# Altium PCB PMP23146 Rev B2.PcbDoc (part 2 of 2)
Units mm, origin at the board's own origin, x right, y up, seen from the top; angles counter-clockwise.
Board outline 35 x 30 mm, 4 copper layers (Top Layer, Int1 (GND), Int2 (PWR), Bottom Layer), stack 0.912 mm thick; 83 components, 52 nets, 312 pads, 74 vias.
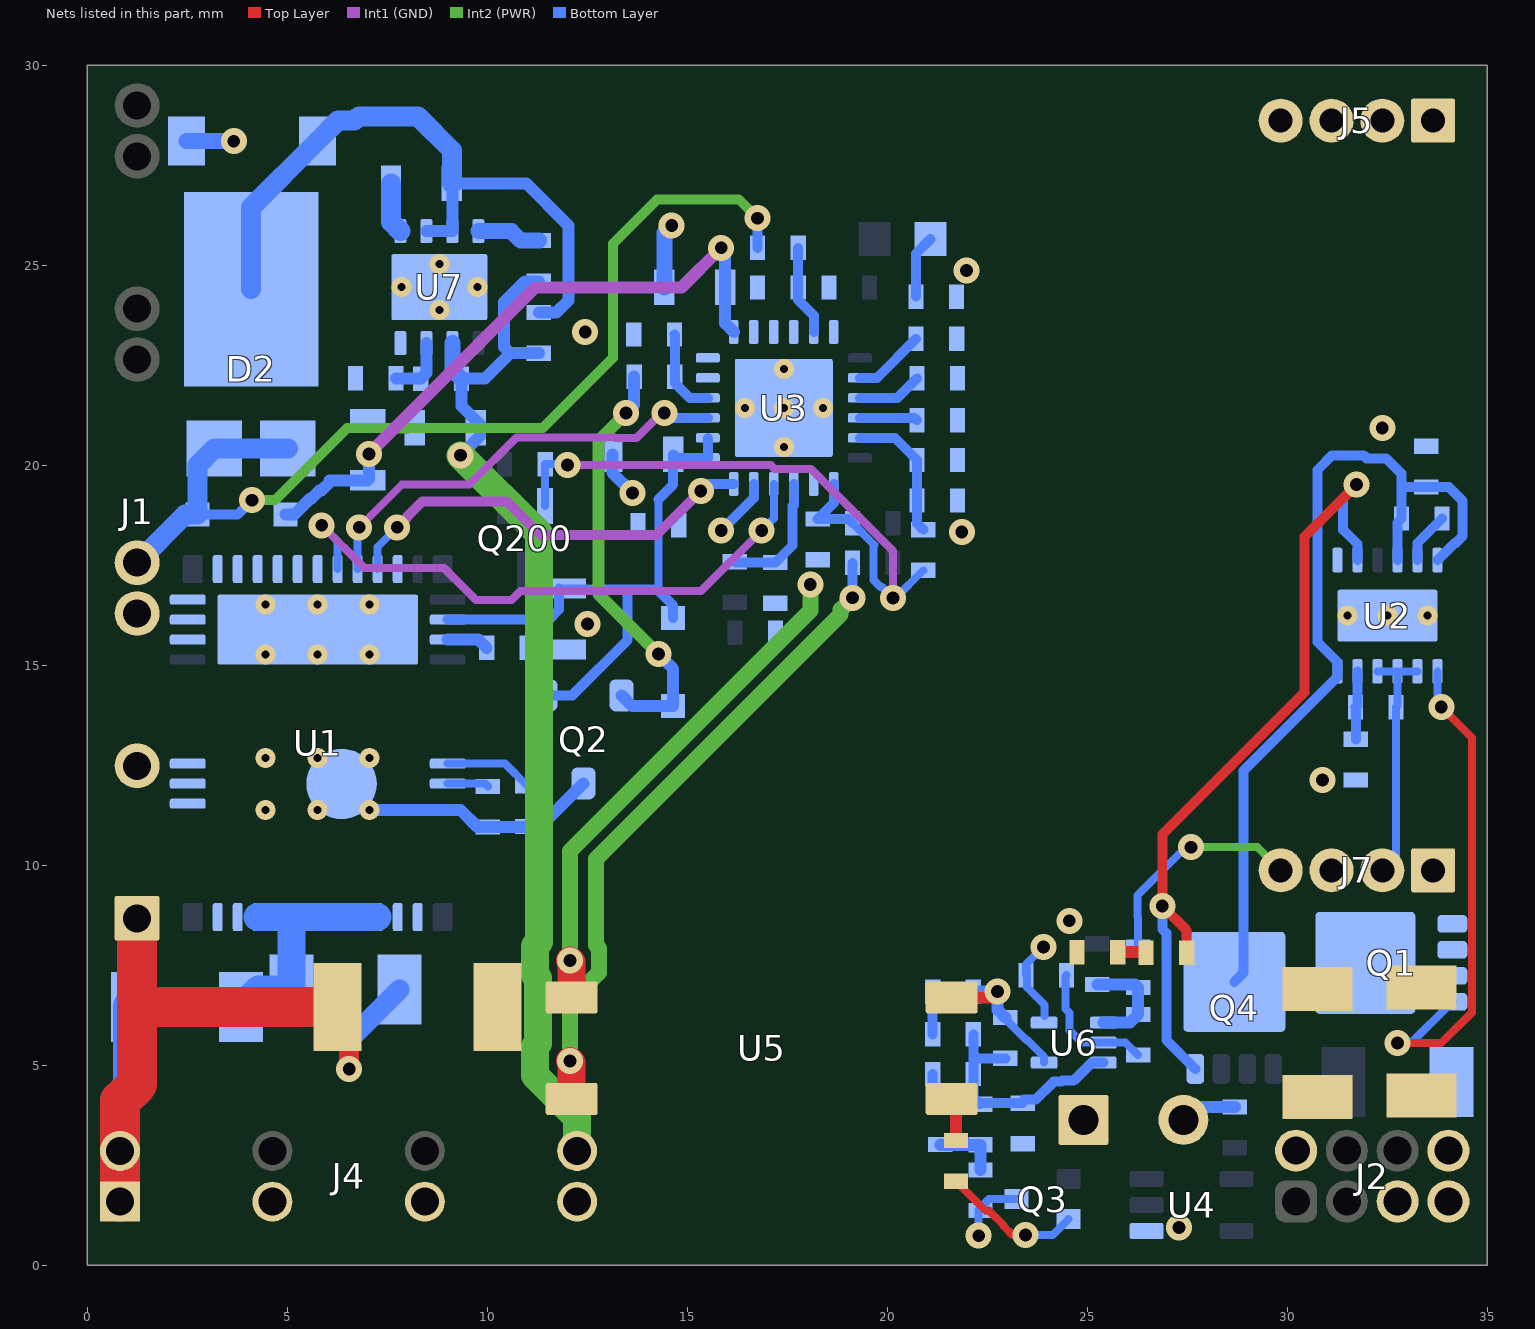
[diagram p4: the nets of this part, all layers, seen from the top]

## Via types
v1: diameter 0.65, hole 0.32, Top Layer to Bottom Layer, 41 vias
v2: diameter 0.5, hole 0.2, Top Layer to Bottom Layer, 24 vias
v3: diameter 0.65, hole 0.32, Top Layer to Bottom Layer, tented bottom, 9 vias

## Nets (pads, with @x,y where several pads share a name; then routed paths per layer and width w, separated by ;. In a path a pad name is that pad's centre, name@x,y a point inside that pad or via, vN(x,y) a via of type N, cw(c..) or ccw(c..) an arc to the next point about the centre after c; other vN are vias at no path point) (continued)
GND: C4.1 C5.1 C6.2 C8.2 C19.1 C22.1 C25.1 J2.5 J2.7 J2.8 R3.2 R16.1 R32.1 U2.7 U2.13 U4.1 U6.2 | length 3.4
  Bottom Layer w0.2: C19.1@24.481,7.255 24.453,7.226 24.453,6.414 24.555,6.312 24.555,5.874 24.863,5.567 U6.2@25.4,5.567 25.958,5.567 C22.1@26.269,5.256
  other v1: 27.295,0.946 24.551,8.612 30.88,12.131 32.373,20.934
  other v2: 31.504,16.239 32.504,16.239 33.504,16.239
ICGND: C12.2 C15.1 C17.2 C20.1 C21.2 C23.2 R8.1 R13.1 R18.1 R21.1 R22.1 R23.1 R24.1 R25.2 U3.8 U3.17 U3.18 U3.20 U3.21 U3.22 U3.24 U3.25 U5.4 | length 15.6
  Top Layer w0.7: v1(12.069,7.622) 12.11,7.582 U5.4@12.11,6.699
  Int2 (PWR) w0.4: v1(12.069,7.622) 12.069,10.364 18.074,16.368 v1(18.074,17.023)
  Bottom Layer w0.3: C15.1@13.124,20.274 13.124,19.817 v1(13.631,19.31)
  Bottom Layer w0.4: C12.2@14.424,24.449 14.424,25.81 v1(14.61,25.996)
  other v1: 21.861,18.332 21.978,24.869
  other v2: 17.411,20.459 16.436,21.434 17.411,21.434 18.386,21.434 17.411,22.409
ISNS: J5.3 J5.4 J7.3 J7.4 R3.1 R20.1 | length 5.6
  Int2 (PWR) w0.2: v1(27.594,10.454) 29.256,10.454 J7.4@29.835,9.875
  Bottom Layer w0.2: R20.1@26.269,7.958 26.269,8.706 26.25,8.725 26.25,9.242 27.462,10.454 v1(27.594,10.454)
NetC1_2: C1.2 R1.1 U1.2 U1.3 U1.4 U1.5 U1.6 U1.7 U1.8 U1.9 U1.10 U1.11 U1.12 | length 6.3
  Bottom Layer w0.7: C1.2@3.837,6.46 4.276,6.899 R1.1@5.107,6.899 5.107,8.553 U1.8@5.261,8.707 ; U1.10@4.261,8.707 U1.9@4.761,8.707 U1.8@5.261,8.707 ; U1.4@7.261,8.707 U1.5@6.761,8.707 U1.6@6.261,8.707 U1.7@5.761,8.707 U1.8@5.261,8.707
NetC2_1: C2.1 U1.38 | length 2.2
  Bottom Layer w0.2: U1.38@9.011,12.542 10.445,12.542 C2.1@10.999,11.987
NetC8_1: C8.1 C11.1 Q1.5 Q1.6 Q1.7 Q1.8 Q1.9@31.949,7.562 Q4.5 Q4.6 Q4.7 Q4.8 Q4.9@28.675,7.086 U2.6 U2.10 U2.12 | length 22.2
  Bottom Layer w0.25: Q4.9@28.675,7.086 28.91,7.321 28.91,12.368 31.254,14.712 U2.6@31.254,14.849 31.254,15.081 30.754,15.581 30.754,19.886 31.119,20.25 31.91,20.25 31.985,20.176 32.465,20.176 32.848,19.792 32.848,19.478 ; U2.10@32.754,17.629 32.754,18.571 C11.1@32.854,18.671 32.848,18.677 32.848,19.478 ; U2.12@33.754,17.629 34.166,18.041 34.195,18.041 34.386,18.232 34.386,19.111 34.036,19.46 C8.1@33.469,19.46 32.866,19.46 32.848,19.478
NetC9_1: C9.1 D2.3 D101.1 R26.1 U7.6 U7.7 | length 17.1
  Bottom Layer w0.3: U7.6@8.475,25.854 U7.7@9.125,25.854 9.125,27.04 C9.1@9.115,27.051 10.969,27.051 12.026,25.994 12.026,24.118 11.727,23.819 R26.1@11.289,23.819
  Bottom Layer w0.5: D2.3@4.095,24.405 4.095,26.451 D101.1@5.755,28.11 6.261,28.617 6.68,28.617 6.789,28.726 8.262,28.726 9.115,27.873 C9.1@9.115,27.051
NetC11_2: C11.2 U2.11 | length 1.3
  Bottom Layer w0.25: U2.11@33.254,17.629 33.254,18.055 C11.2@33.87,18.671
NetC14_1: C14.1 R10.1 U5.3 U6.4 | length 4.1
  Top Layer w0.3: U5.3@21.61,6.699 22.615,6.699 v1(22.758,6.843)
  Bottom Layer w0.2: C14.1@22.951,6.193 22.951,6.155 23.428,5.678 23.49,5.617 23.516,5.617 23.92,5.213 U6.4@23.92,5.067
  Bottom Layer w0.3: R10.1@22.15,6.843 v1(22.758,6.843) 22.758,6.385 C14.1@22.951,6.193
NetC14_2: C14.2 C16.1 R11.1 R16.2 R201.1 U6.3 | length 6.1
  Bottom Layer w0.25: C16.1@22.15,5.775 22.15,5.279 ; C14.2@22.951,5.177 22.252,5.177 22.15,5.279 ; R16.2@23.384,4.053 22.353,4.053 R11.1@22.328,4.029 22.15,4.207 R201.1@22.15,4.784 22.15,5.279 ; R16.2@23.412,4.144 23.713,4.144 24.16,4.592 24.361,4.592 24.386,4.617 24.66,4.617 25.11,5.067 U6.3@25.4,5.067
NetC16_2: C16.2 R10.2 | length 1.1
  Bottom Layer w0.25: C16.2@21.134,5.775 R10.2@21.134,6.843
NetC17_1: C17.1 R9.2 U3.9 | length 3.2
  Bottom Layer w0.25: R9.2@16.19,17.591 16.212,17.569 C17.1@17.202,17.569 17.63,17.997 17.63,18.982 17.661,19.013 U3.9@17.661,19.534
NetC20_2: C20.2 R15.1 R18.2 U3.5 | length 3.5
  Bottom Layer w0.25: U3.5@19.311,20.684 20.191,20.684 C20.2@20.741,20.134 R18.2@20.741,19.119 20.741,18.55 R15.1@20.899,18.392
NetC22_2: C22.2 R19.2 R20.2 U6.1 | length 2.7
  Bottom Layer w0.3: R19.2@25.248,7.024 26.187,7.024 R20.2@26.269,6.942 C22.2@26.269,6.272 26.064,6.067 U6.1@25.4,6.067
NetC25_2: C25.2 R27.1 | length 0.7
  Top Layer w0.3: C25.2@25.759,7.828 26.456,7.828 R27.1@26.467,7.817
NetC100_1: C100.1 R201.2 | length 0.8
  Bottom Layer w0.25: R201.2@21.134,4.784 21.134,4.229 C100.1@21.327,4.035
NetC100_2: C100.2 R11.2 R12.2 | length 1.6
  Bottom Layer w0.3: C100.2@21.327,3.019 21.334,3.013 R11.2@22.328,3.013 R12.2@22.328,2.385
NetD3_1: D3.1 Q2.2 R5.2 | length 10.8
  Int2 (PWR) w0.3: v1(13.47,21.307) 12.78,20.617 12.78,16.778 v1(14.276,15.282)
  Bottom Layer w0.3: Q2.2@13.355,14.25 13.624,13.981 D3.1@14.648,13.981 14.648,14.91 v1(14.276,15.282) ; v1(13.47,21.307) 13.672,21.509 R5.2@13.672,22.218
NetQ1_4: Q1.4 U2.1 | length 12.9
  Top Layer w0.2: v1(32.758,5.556) 33.847,5.556 34.616,6.324 34.616,13.189 v1(33.848,13.956)
  Bottom Layer w0.2: v1(32.758,5.556) 33.093,5.556 Q1.4@34.124,6.587 ; U2.1@33.754,14.849 33.754,14.05 v1(33.848,13.956)
NetQ3_2: Q3.2 R14.2 | length 3.6
  Top Layer w0.2: R14.2@21.718,2.101 22.453,1.366 22.542,1.366 22.908,1 22.908,0.979 23.131,0.756 v1(23.454,0.756)
  Bottom Layer w0.2: v1(23.454,0.756) 24.134,0.756 Q3.2@24.534,1.156
NetQ4_4: Q4.4 R27.2 U2.8 | length 20.6
  Top Layer w0.25: R27.2@27.483,7.817 27.483,8.376 v1(26.875,8.984) 26.875,10.767 30.425,14.317 30.425,14.381 30.434,14.381 30.434,18.222 v1(31.733,19.521)
  Bottom Layer w0.25: v1(26.875,8.984) 26.875,8.408 26.975,8.308 26.975,5.636 Q4.4@27.7,4.911 ; v1(31.733,19.521) 31.396,19.184 31.396,18.388 31.491,18.293 31.754,18.03 U2.8@31.754,17.629
NetR2_2: R2.2 U1.39 | length 1
  Bottom Layer w0.2: U1.39@9.011,12.042 9.946,12.042 R2.2@10.015,11.973
NetR4_1: R4.1 U1.36 | length 1.1
  Bottom Layer w0.3: U1.36@9.011,15.642 9.78,15.642 R4.1@9.983,15.438
NetR6_1: R6.1 R8.2 U3.23 | length 2.3
  Bottom Layer w0.25: R6.1@17.772,25.438 R8.2@17.772,24.444 17.772,24.136 18.161,23.747 U3.23@18.161,23.334
NetR14_1: R14.1 U5.1 | length 1.1
  Top Layer w0.3: U5.1@21.61,4.159 21.718,4.052 R14.1@21.718,3.117
NetR17_2: R17.2 U5.6 | length 16.5
  Top Layer w0.7: v1(12.069,5.11) 12.11,5.069 U5.6@12.11,4.159
  Int2 (PWR) w0.4: v1(12.069,5.11) 12.069,6.674 12.293,6.897 12.37,6.897 12.794,7.322 12.794,7.923 12.712,8.005 12.712,10.157 18.831,16.276 18.831,16.39 v1(19.128,16.687)
  Bottom Layer w0.25: v1(19.128,16.687) R17.2@19.128,17.561
NetR21_2: R21.2 U3.2 | length 1.8
  Bottom Layer w0.25: U3.2@19.311,22.184 19.741,22.184 R21.2@20.719,23.162
NetR22_2: R22.2 RT1.2 | length 1.6
  Bottom Layer w0.25: R22.2@20.716,24.216 20.716,25.295 RT1.2@21.075,25.654
NetR23_2: R23.2 U3.3 | length 1.6
  Bottom Layer w0.25: U3.3@19.311,21.684 20.25,21.684 R23.2@20.741,22.176
NetR24_2: R24.2 U3.4 | length 1.5
  Bottom Layer w0.25: U3.4@19.311,21.184 20.686,21.184 R24.2@20.741,21.129
NetR28_1: R28.1 U7.8 | length 1.6
  Bottom Layer w0.4: U7.8@9.775,25.854 10.6,25.854 10.837,25.617 R28.1@11.289,25.617
NetR29_1: R29.1 R31.2 U7.3 | length 1.6
  Bottom Layer w0.3: R31.2@7.719,22.176 7.726,22.168 R29.1@8.337,22.168 8.475,22.307 U7.3@8.475,23.054
NetR30_1: R30.1 R32.2 U2.5 | length 1.7
  Bottom Layer w0.25: R30.1@31.704,13.956 R30.1@31.715,13.945 ; R32.2@31.715,13.15 R30.1@31.715,13.945 ; U2.5@31.754,14.849 31.754,13.984 R30.1@31.715,13.945
P13: C3.2 C15.2 D3.2 Q2.1 U1.35 U3.13 U3.14 | length 15.6
  Bottom Layer w0.2: 14.276,16.868 14.276,19.146
  Bottom Layer w0.25: U1.35@9.011,16.142 11.536,16.142 11.789,16.395 11.789,16.919 11.817,16.891 13.501,16.891 ; Q2.1@11.455,14.25 12.123,14.25 13.501,15.628 13.501,16.891 ; 14.276,19.146 14.648,19.518 C15.2@14.648,20.274 14.738,20.184 U3.13@15.511,20.184 U3.14@15.511,20.684 ; D3.2@14.648,16.181 14.648,16.496 14.276,16.868 14.253,16.891 13.501,16.891
P18V: C13.1 J4.20 R26.2 R28.2 R29.2 U7.2 | length 26.7
  Int2 (PWR) w0.7: v3(9.332,20.25) 11.289,18.293 11.289,8.079 11.194,7.985 11.194,7.26 11.272,7.183 11.272,5.549 11.194,5.472 11.194,4.747 12.247,3.694 J4.20@12.247,2.86
  Bottom Layer w0.3: v3(9.332,20.25) 9.813,20.731 9.813,21.028 9.353,21.488 R29.2@9.353,22.168 9.937,22.168 10.572,22.803 ; R26.2@11.289,22.803 10.572,22.803 ; R28.2@11.289,24.601 10.939,24.601 10.422,24.085 10.422,22.954 10.572,22.803
  Bottom Layer w0.4: U7.2@9.125,23.054 9.125,22.396 R29.2@9.353,22.168
PWMH: U1.29 U3.15 | length 11
  Int1 (GND) w0.2: v3(6.798,18.449) 7.873,19.524 9.553,19.524 10.727,20.698 13.195,20.698 13.211,20.682 13.729,20.682 14.354,21.307 v1(14.424,21.307)
  Bottom Layer w0.2: U1.29@6.761,17.407 6.761,18.412 v3(6.798,18.449)
  Bottom Layer w0.25: v1(14.424,21.307) 14.547,21.184 U3.15@15.511,21.184
PWML: U1.30 U3.12 | length 10.8
  Int1 (GND) w0.25: v3(7.746,18.449) 7.996,18.699 7.996,18.719 8.377,19.099 10.483,19.099 11.327,18.255 14.232,18.255 v1(15.336,19.359)
  Bottom Layer w0.2: U1.30@7.261,17.407 7.261,17.964 v3(7.746,18.449)
  Bottom Layer w0.25: v1(15.336,19.359) 15.511,19.534 U3.12@16.161,19.534
PWRGND: C3.1 C7.2 C9.2 C10.1 C13.2 C24.2 D101.2 J1.7 J4.7 J4.13 J4.19 R4.2 R25.1 R31.1 U1.18 U1.19 U1.20 U1.22 U1.23 U1.24 U1.25 U1.26 U1.27 U1.31 U1.42 U3.11 U7.4 U7.5 U7.9@8.8,24.454 | length 4
  Bottom Layer w0.25: v1(15.848,18.37) 16.661,19.183 U3.11@16.661,19.534
  Bottom Layer w0.4: D101.2@2.48,28.11 3.655,28.11 v1(3.663,28.103)
  Bottom Layer w0.5: C9.2@7.591,27.051 7.591,26.088 U7.5@7.825,25.854
  other v2: 4.461,15.267 5.761,15.267 7.061,15.267 4.461,16.517 5.761,16.517 7.061,16.517 8.8,23.879 7.85,24.454 9.75,24.454 8.8,25.029
  other v3: 12.503,16.035 12.447,23.334
REF: C18.2 C23.1 Q200.2 R15.2 R200.2 U3.7 | length 17.2
  Int1 (GND) w0.2: v1(12.002,20.006) 17.086,20.006 17.183,19.909 18.096,19.909 20.144,17.861 v1(20.144,16.68)
  Bottom Layer w0.2: Q200.2@11.439,18.977 11.439,20.021 R200.2@11.447,20.029 11.979,20.029 v1(12.002,20.006) ; C18.2@19.128,18.555 19.674,18.01 19.654,17.99 19.654,17.132 19.751,17.034 19.829,16.956 19.869,16.956 v1(20.144,16.68) 20.204,16.68 R15.2@20.899,17.376
  Bottom Layer w0.25: U3.7@18.661,19.534 18.661,19.058 C23.1@18.26,18.657 19.026,18.657 C18.2@19.128,18.555
RUN: U1.28 U3.10 | length 15
  Int1 (GND) w0.2: v3(5.861,18.499) 6.928,17.432 8.915,17.432 9.715,16.632 10.606,16.632 10.829,16.855 15.345,16.855 v1(16.86,18.37)
  Bottom Layer w0.2: v3(5.861,18.499) 6.261,18.099 U1.28@6.261,17.407 ; v1(16.86,18.37) 17.161,18.671 U3.10@17.161,19.534
S12V: C4.2 C5.2 C19.2 J2.2 J5.1 J5.2 J7.1 J7.2 Q1.1 Q1.2 Q1.3 Q3.3 R7.2 R12.1 R30.2 U2.2 U2.3 U2.4 U6.5 | length 11.6
  Bottom Layer w0.2: v1(22.283,0.741) 22.283,1.396 22.328,1.441 22.544,1.656 Q3.3@23.234,1.656 ; C19.2@23.465,7.255 23.465,7.525 v1(23.902,7.961) ; C19.2@23.497,7.437 23.497,6.942 23.934,6.505 23.934,6.234 ; U2.4@32.254,14.849 U2.3@32.754,14.849 ; J7.2@32.375,9.875 32.72,10.22 R30.2@32.72,13.956 32.754,13.99 U2.3@32.754,14.849 ; U2.2@33.254,14.849 U2.3@32.754,14.849
  Bottom Layer w0.3: C4.2@27.303,3.736 27.524,3.957 R7.2@28.688,3.957
SWS: C10.2 R5.1 U3.16 | length 2.2
  Bottom Layer w0.25: C10.2@14.678,23.272 14.688,23.262 R5.1@14.688,22.218 14.688,22.06 15.063,21.684 U3.16@15.511,21.684
VAUX: D1.2 D2.1 D2.2 J1.8 R6.2 | length 25.9
  Int2 (PWR) w0.25: v3(4.117,19.128) 4.69,19.128 6.497,20.934 8.018,20.934 ; 7.624,20.925 8.009,20.925 8.018,20.934 ; v1(16.756,26.179) 16.289,26.646 14.341,26.646 14.34,26.645 14.246,26.645 13.142,25.54 13.142,22.689 11.387,20.934 8.018,20.934
  Bottom Layer w0.25: D1.2@2.757,18.769 3.758,18.769 v3(4.117,19.128) ; R6.2@16.756,25.438 v1(16.756,26.179)
  Bottom Layer w0.5: J1.8@1.245,17.566 2.448,18.769 D1.2@2.757,18.769 2.757,20.005 D2.2@3.175,20.423 D2.1@5.015,20.423
VDCIN: C1.1 C24.1 J1.1 J4.1 J4.2 R1.2 | length 23.8
  Top Layer w0.5: C24.1@6.261,6.46 6.546,6.174 v1(6.546,4.911)
  Top Layer w1: J4.1@0.817,1.59 J4.2@0.817,2.86 0.817,4.104 1.245,4.532 1.245,6.46 ; J1.1@1.245,8.676 1.245,6.46 ; 1.305,6.399 1.245,6.46 ; C24.1@6.261,6.46 1.245,6.46
  Bottom Layer w0.5: v1(6.546,4.911) 6.546,5.638 R1.2@7.807,6.899
  Bottom Layer w1: J4.1@0.817,1.59 J4.2@0.817,2.86 0.817,4.104 1.137,4.424 C1.1@1.137,6.46 1.245,6.568 J1.1@1.245,8.676
VDD: C7.1 C12.1 D1.1 U3.19 | length 16.3
  Int1 (GND) w0.3: v1(7.039,20.284) 11.2,24.444 14.854,24.444 v1(15.848,25.438)
  Bottom Layer w0.3: D1.1@4.957,18.769 5.186,18.769 5.186,18.779 5.581,19.174 5.611,19.174 5.809,19.373 5.855,19.373 6.06,19.578 6.06,19.627 C7.1@7.011,19.627 7.039,19.655 v1(7.039,20.284) ; v1(15.848,25.438) 15.948,25.338 C12.1@15.948,24.449 15.948,23.547 U3.19@16.161,23.334
VSWN: C2.2 J1.4 Q2.3 R2.1 U1.14 U1.15 U1.16 U1.40-41 | length 6
  Bottom Layer w0.3: v2(7.061,11.387) 9.326,11.387 9.755,10.957 R2.1@10.015,10.957 10.985,10.957 C2.2@10.999,10.971 11.326,10.971 Q2.3@12.405,12.05
  other v2: 4.461,11.387 5.761,11.387 4.461,12.687 5.761,12.687 7.061,12.687
pads on no net: J1.12 J1.13 J1.16 J1.17 J2.1 J4.8 Q1.9@31.424,6.587 Q1.9@31.424,7.237 Q1.9@31.424,7.887 Q1.9@31.424,8.537 Q1.9@31.935,6.899 Q1.9@31.935,8.224 Q1.9@32.272,7.562 Q1.9@32.811,6.899 Q1.9@32.811,8.224 Q4.9@27.7,7.611 Q4.9@28.013,6.224 Q4.9@28.013,7.1 Q4.9@28.35,7.611 Q4.9@28.675,6.764 Q4.9@29,7.611 Q4.9@29.65,7.611 Q4.9@29.338,6.224 Q4.9@29.338,7.1 U1.1 U1.13 U1.17 U1.21 U1.33 U1.37 U4.2 U4.4 U4.5 U7.1 U7.9@8.17,24.454 U7.9@9.43,24.454

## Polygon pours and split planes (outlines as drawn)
NetC1_2 on Bottom Layer "BOTTOM_LAYER_NETC1_2_P031" (solid, remove dead copper, pour order 31): 3.095,9.089 3.095,8.306 8.409,8.306 8.409,9.089
GND on Bottom Layer "BOTTOM_LAYER_GND_P025" (solid, remove dead copper, pour order 25): 30.393,30 30.393,0 35,0 35,30
S12V on Bottom Layer "BOTTOM_LAYER_12VSA_P023" (solid, remove dead copper, pour order 23): 31.715,10.491 31.715,6.927 34.848,6.927 34.848,10.491
NetC8_1 on Bottom Layer "BOTTOM_LAYER_NETC8_1_P006" (solid, remove dead copper, pour order 6): 27.271,8.98 27.271,5.738 33.248,5.738 33.248,8.98
PWRGND on Bottom Layer "BOTTOM_LAYER_PWRGND_P000" (solid, remove dead copper, pour order 0): 0.384,26.454 0.384,15.01 22.328,15.01 22.328,26.454
GND on Bottom Layer "BOTTOM_LAYER_GND_P024" (solid, remove dead copper, pour order 24): 20.974,14.933 20.974,0.13 34.957,0.13 34.957,14.933
12VSB on Bottom Layer "BOTTOM_LAYER_12VSB_P012" (solid, remove dead copper, pour order 12): 28.013,5.592 28.013,1.014 33.348,1.014 33.348,5.592
ICGND on Bottom Layer "BOTTOM_LAYER_ICGND_P002" (solid, remove dead copper, pour order 2): 12.786,26.454 12.786,15.466 22.328,15.466 22.328,26.454
VSWN on Bottom Layer "BOTTOM_LAYER_VSWN_P001" (solid, remove dead copper, pour order 1): 0.635,13.15 0.635,11.073 9.665,11.073 9.665,13.15
S12V on Top Layer "TOP_LAYER_12VSA_P005" (solid, remove dead copper, pour order 5): 31.74,10.454 31.74,6.152 34.708,6.152 34.708,10.454
GND on Top Layer "TOP_LAYER_GND_P007" (solid, remove dead copper, pour order 7): 30.362,30 30.362,10.252 34.969,10.252 34.969,30
ISNS on Top Layer "TOP_LAYER_ISNS_P003" (solid, remove dead copper, pour order 3): 29.269,10.454 29.269,6.152 31.708,6.152 31.708,10.454
VSWN on Top Layer "TOP_LAYER_VSWN_P014" (solid, remove dead copper, pour order 14): 0.639,13 0.639,11.042 7.345,11.042 7.345,13
GND on Top Layer "TOP_LAYER_GND_P030" (solid, remove dead copper, pour order 30): 20.993,15 20.993,0.116 34.976,0.116 34.976,15
PWRGND on Top Layer "TOP_LAYER_PWRGND_P027" (solid, remove dead copper, pour order 27): 0,26.455 0,15.467 22.365,15.467 22.365,26.455
PWRGND on Top Layer "TOP_LAYER_PWRGND_P019" (solid, remove dead copper, pour order 19): 0.089,21.334 0.089,-0.008 12.712,-0.008 12.712,21.334
PWRGND on Int2 (PWR) "INT2_(PWR)_PWRGND_P022" (solid, remove dead copper, pour order 22): 0,29.893 0,0 12.819,0 12.819,29.893
S12V on Int2 (PWR) "INT2_(PWR)_12VSA_P018" (solid, remove dead copper, pour order 18): 20.974,13.392 20.974,0.262 34.867,0.262 34.867,13.392
S12V on Int2 (PWR) "INT2_(PWR)_12VSA_P015" (solid, remove dead copper, pour order 15): 28.904,29.984 28.904,0.642 34.965,0.642 34.965,29.984
ICGND on Int2 (PWR) "INT2_(PWR)_ICGND_P004" (solid, remove dead copper, pour order 4): 12.786,26.454 12.786,15.466 22.328,15.466 22.328,26.454
PWRGND on Int1 (GND) "INT1_(GND)_PWRGND_P021" (solid, remove dead copper, pour order 21): 9.111,26.455 9.111,15.412 22.365,15.412 22.365,26.455
PWRGND on Int1 (GND) "INT1_(GND)_PWRGND_P020" (solid, remove dead copper, pour order 20): -0.167,30 -0.167,0 12.815,0 12.815,30
GND on Int1 (GND) "INT1_(GND)_GND_P016" (solid, remove dead copper, pour order 16): 20.974,13.377 20.974,0 35,0 35,13.377
ISNS on Int1 (GND) "INT1_(GND)_ISNS_P010" (solid, remove dead copper, pour order 10): 28.95,30.051 28.95,8.98 35.012,8.98 35.012,30.051

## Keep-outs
Top Layer:
  lines w0.254: 19.839,15.101 23.211,18.473 ; 22.5,7.5 29.9,14.9
Int1 (GND):
  lines w0.254: 19.839,15.101 23.211,18.473 ; 20.575,7.5 22.5,7.5 28.5,13.5
Int2 (PWR):
  lines w0.254: 19.839,15.101 23.211,18.473 ; 20.575,7.5 22.487,7.5 ; 22.5,7.5 28.5,13.5
Bottom Layer:
  lines w0.254: 19.839,15.101 23.211,18.473 ; 20.575,7.5 22.487,7.5 30,15
Keep-Out Layer:
  text ".Layer_Name" at 14.656,-21.806 h1.52

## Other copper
Top Layer:
  text ".Layer_Name" at 14.656,-21.806 h1.52
Int1 (GND):
  pour cut-out: 8.271,13.25 0,13.25 0,10.915 8.271,10.915
Int2 (PWR):
  pour cut-out: 8.271,13.25 0,13.25 0,10.915 8.271,10.915
Bottom Layer:
  text ".Layer_Name" at 14.656,-21.806 h1.52

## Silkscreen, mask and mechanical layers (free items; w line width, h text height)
Top Overlay:
  text ".Layer_Name" at 14.656,-21.806 h1.52
Bottom Overlay:
  text "PMP23146PCB Rev B2" at 29,28.11 h2
  text ".Layer_Name" at 14.656,-21.806 h1.52
Top Paste:
  text ".Layer_Name" at 14.656,-21.806 h1.52
Bottom Paste:
  text ".Layer_Name" at 14.656,-21.806 h1.52
Top Solder:
  text ".Layer_Name" at 14.656,-21.806 h1.52
  text ".Layer_Name" at 14.656,-21.806 h1.52
Bottom Solder:
  text ".Layer_Name" at 14.656,-21.806 h1.52
Drill Guide:
  text ".Layer_Name" at 14.656,-21.806 h1.52
M1 Board Outline:
  the board outline again, w0.254
  text ".Layer_Name" at 14.656,-21.806 h1.52
M2 Board Dimensions:
  rectangle: 0,-6.985 3.175,-3.81
  rectangle: 3.175,-10.16 12.7,-6.985
  lines w0.178: 0,-6.985 25.4,-6.985 ; 3.175,-10.16 3.175,-3.81 ; 6.35,-10.16 6.35,-3.81 ; 12.7,-10.16 12.7,-3.81 ; 19.05,-10.16 19.05,-3.81 ; 0,-10.16 25.4,-10.16 25.4,-3.81 0,-3.81 0,-10.16
  text ".Layer_Name" at 14.656,-21.806 h1.52
M3 3D STEP Top:
  text ".Layer_Name" at 14.656,-21.806 h1.52
M4 3D STEP Bottom:
  text ".Layer_Name" at 14.656,-21.806 h1.52
M5 Assembly Top:
  lines w0.254: -7.417,-23.626 160.223,-23.626 ; -7.417,-18.462 160.274,-18.462 ; -7.417,-13.297 -7.417,-28.791 94.31,-28.791 160.274,-28.791 160.274,-13.297 -7.404,-13.297 -7.404,-28.791 32.614,-28.791 ; 55.194,-28.791 55.194,-13.297 ; 87.376,-18.462 87.376,-13.297 ; 108.712,-18.462 108.712,-13.297 ; 124.511,-28.956 124.511,-23.804
  text "COMPONENTS MARKED 'DNP' SHOULD NOT BE POPULATED." at 29.299,-8.09 h1.52
  text "ASSEMBLY VARIANT:" at 29.286,-11.024 h1.52
  text ".VariantName" at 55.601,-11.024 h1.52
  text "PCB VIEWED FROM TOP SIDE" at -5.804,-16.654 h1.52
  text "BOARD #:" at 57.099,-16.654 h1.52
  text ".PRJ_Number" at 70.955,-16.654 h1.52
  text "REV:" at 92.405,-16.654 h1.52
  text ".PCB_Rev" at 99.809,-16.654 h1.52
  text "SVN REV:" at 113.69,-16.654 h1.52
  text ".VersionControl_RevNumber" at 126.543,-16.654 h1.52
  text "TID #:" at 57.099,-21.819 h1.52
  text ".TID" at 70.955,-21.819 h1.52
  text "PLOT NAME =" at -5.804,-27.034 h1.52
  text ".plot_File_Name" at 14.656,-27.034 h1.52
  text "GENERATED    :" at 57.15,-27.034 h1.52
  text ".Print_Date" at 79.235,-27.034 h1.52
  text ".Print_Time" at 97.752,-27.034 h1.52
  text "TEXAS INSTRUMENTS" at 129.87,-27.034 h1.52
M6 Assembly Bottom:
  lines w0.254: -7.429,-18.474 160.261,-18.474 ; -7.379,-23.639 160.261,-23.639 ; 28.334,-28.969 28.334,-23.817 ; 44.133,-18.474 44.133,-13.31 ; 65.468,-18.474 65.468,-13.31 ; 97.65,-28.804 97.65,-13.31 ; 120.231,-28.804 160.249,-28.804 160.249,-13.31 -7.429,-13.31 -7.429,-28.804 58.534,-28.804 160.261,-28.804 160.261,-13.31
  text "COMPONENTS MARKED 'DNP' SHOULD NOT BE POPULATED." at 154.991,-8.077 h1.52
  text ".VariantName" at 128.473,-11.024 h1.52
  text "ASSEMBLY VARIANT:" at 154.864,-11.024 h1.52
  text ".VersionControl_RevNumber" at 26.302,-16.667 h1.52
  text "SVN REV:" at 39.154,-16.667 h1.52
  text ".PCB_Rev" at 53.035,-16.667 h1.52
  text "REV:" at 60.439,-16.667 h1.52
  text ".PRJ_Number" at 81.89,-16.667 h1.52
  text "BOARD #:" at 95.745,-16.667 h1.52
  text "PCB VIEWED FROM BOTTOM SIDE" at 158.648,-16.667 h1.52
  text ".TID" at 81.89,-21.831 h1.52
  text "TID #:" at 95.745,-21.831 h1.52
  text "TEXAS INSTRUMENTS" at 22.974,-27.047 h1.52
  text ".Print_Time" at 55.093,-27.047 h1.52
  text ".Print_Date" at 73.609,-27.047 h1.52
  text "GENERATED    :" at 95.694,-27.047 h1.52
  text ".plot_File_Name" at 138.189,-27.047 h1.52
  text "PLOT NAME =" at 158.648,-27.047 h1.52
M9 Title Sheet:
  drawing of 57 lines, arcs and shapes, not listed
  text "1" at 18.792,204.127 h1.78
  text "2" at 82.182,204.127 h1.78
  text "3" at 145.411,204.127 h1.78
  text "4" at 209.08,204.127 h1.78
  text "5" at 272.555,204.127 h1.78
  text "6" at 336.182,204.127 h1.78
  text "A" at -10.579,175.095 h1.78
  text "A" at 365.341,175.095 h1.78
  text "B" at -10.579,114.643 h1.78
  text "B" at 365.341,114.643 h1.78
  text "C" at -10.579,54.318 h1.78
  text "C" at 365.341,54.318 h1.78
  text "PROJECT TITLE:" at 288.125,7.048 h1.14
  text ".PRJ_Title" at 289.395,3.662 h1.78
  text "DESIGNED FOR:" at 288.125,-0.597 h1.14
  text ".PRJ_Customer" at 289.395,-4.153 h1.78
  text "D" at -10.579,-5.88 h1.78
  text "D" at 365.341,-5.88 h1.78
  text "FILE NAME:" at 288.125,-8.217 h1.14
  text ".PCB_File_Name_No_Path" at 289.395,-11.265 h1.78
  text "Texas Instruments (TI) and/or its licensors do not warrant the accuracy or completeness of this specification" at 161.9,-15.376 h1.14
  text "ENGINEER:" at 288.125,-15.583 h1.14
  text "LAYOUT BY:" at 326.352,-15.583 h1.14
  text "or any information contained therein. TI and/or its licensors do not warrant that this design will meet" at 160.757,-18.237 h1.14
  text ".PRJ_Engineer" at 289.395,-19.52 h1.78
  text ".PCB_Layout" at 327.635,-19.52 h1.78
  text "the specifications, will be suitable for your application or fit for any particular purpose, or will operate in" at 160.757,-21.099 h1.14
  text ".Layer_Name" at 14.656,-21.806 h1.52
  text "ALTIUM DESIGNER VERSION:" at 326.352,-23.457 h1.14
  text "an implementation. TI and/or its licensors do not warrant that the design is production worthy. You should" at 160.757,-23.961 h1.14
  text "completely validate and test your design implementation to confirm the system functionality for your application." at 161.9,-26.822 h1.14
  text ".print_Scale" at 289.395,-26.843 h1.78
  text ".Application_BuildNumber" at 327.635,-26.843 h1.78
  text "1" at 18.792,-32.093 h1.78
  text "2" at 82.182,-32.093 h1.78
  text "3" at 145.411,-32.093 h1.78
  text "4" at 209.08,-32.093 h1.78
  text "5" at 272.555,-32.093 h1.78
  text "6" at 336.182,-32.093 h1.78
M10 Fab Notes:
  drawing of 189 lines, arcs and shapes, not listed
  text "DESIGN INFORMATION" at 314.503,161.447 h1.52
  text "MIN. TRACK WIDTH:" at 298.131,158.091 h1.52
  text "8" at 325.976,158.091 h1.52
  text "MIL" at 329.907,158.091 h1.52
  text "7.874" at 321.75,155 h1.52
  text "MIN. CLEARANCE:" at 298.131,154.938 h1.52
  text "MIL" at 329.907,154.938 h1.52
  text "MIN. VIA PAD SIZE:" at 298.131,151.785 h1.52
  text "24" at 325.214,151.785 h1.52
  text "MIL" at 329.907,151.785 h1.52
  text "0.05mm (2MIL)" at 315.784,148.486 h1.52
  text "MINIMUM ANNULAR RING" at 289.769,148.277 h1.52
  text "EXTERNAL" at 333.768,148.277 h1.52
  text "PER" at 294.849,145.48 h1.52
  text "IPC-D-275 CLASS 2 LEVEL C" at 300.437,145.48 h1.52
  text "MIL, HOLES" at 338.238,142.928 h1.52
  text "+/-" at 328.27,142.709 h1.52
  text "+/-" at 349.961,142.709 h1.52
  text "REGISTRATION TOLERANCES:" at 289.769,142.682 h1.52
  text "METAL" at 320.243,142.682 h1.52
  text "5" at 334.879,142.683 h1.52
  text "3" at 356.037,142.683 h1.52
  text "MIL" at 358.99,142.682 h1.52
  text "HOLE SIZE TOLERANCE (UNLESS OTHERWISE SPECIFIED):" at 289.769,140.185 h1.52
  text "+/-" at 349.961,140.112 h1.52
  text "3" at 356.037,140.085 h1.52
  text "MIL" at 358.99,140.085 h1.52
  text "MATERIAL:" at 287.87,136.589 h1.52
  text "FR-4 High Tg" at 312.926,133.324 h1.52
  text "X" at 309.257,133.122 h1.52
  text "FR-408" at 298.563,133.007 h1.52
  text "OTHER" at 336.358,133.007 h1.52
  text "62 MIL (1.6mm) +/-10%" at 306.694,129.374 h1.52
  text "X" at 303.643,129.312 h1.52
  text "THICKNESS:" at 289.769,129.165 h1.52
  text "OTHER" at 339.33,129.165 h1.52
  text "TOLERANCE:" at 289.769,125.652 h1.52
  text "X" at 311.314,125.652 h1.52
  text "ANSI IPC-6012 TYPE 3 CLASS 2" at 315.836,125.652 h1.52
  text "OTHER +/-" at 315.835,121.989 h1.52
  text "BOW & TWIST:" at 289.769,118.302 h1.52
  text "X" at 311.314,118.302 h1.52
  text "ANSI IPC-6012 TYPE 3 CLASS 2" at 315.836,118.302 h1.52
  text "OTHER +/-" at 315.835,114.576 h1.52
  text "DRILLING:" at 287.87,111.258 h1.52
  text "NC_DRILL FILES" at 332.599,108.586 h1.52
  text "REFERENCE:" at 289.769,108.486 h1.52
  text "X" at 306.463,108.484 h1.52
  text "AS SHOWN" at 310.984,108.486 h1.52
  text "X" at 329.348,108.486 h1.52
  text "OTHER" at 340.168,104.873 h1.52
  text "PTH COPPER THICKNESS:" at 289.761,104.783 h1.52
  text "X" at 318.697,104.783 h1.52
  text "20-30 um" at 321.948,104.783 h1.52
  text "BOARD FINISH:" at 287.87,101.034 h1.52
  text "SILKSCREEN:" at 291.812,98.237 h1.52
  text "X" at 316.14,98.237 h1.52
  text "TOP" at 319.112,98.237 h1.52
  text "X" at 329.094,98.237 h1.52
  text "BOTTOM" at 332.091,98.237 h1.52
  text "SILKSCREEN COLOR:" at 291.812,94.295 h1.52
  text "X" at 316.115,94.295 h1.52
  text "WHITE" at 319.112,94.295 h1.52
  text "OTHER" at 332.091,94.295 h1.52
  text "X" at 319.442,90.652 h1.52
  text "GREEN" at 322.439,90.652 h1.52
  text "OTHER" at 338.136,90.652 h1.52
  text "SOLDER RESIST COLOR:" at 291.812,90.477 h1.52
  text "X" at 319.442,86.734 h1.52
  text "MATTE" at 322.439,86.734 h1.52
  text "SEMI-GLOSS" at 338.125,86.717 h1.52
  text "IMMERSION GOLD (ENIG)" at 314.819,82.345 h1.52
  text "ENEPIG" at 348.793,82.162 h1.52
  text "SURFACE FINISH:" at 287.87,82.136 h1.52
  text "X" at 310.298,82.136 h1.52
  text "IMM. TIN/SILVER OR EQUIV" at 296.24,78.649 h1.52
  text "OTHER" at 332.599,78.549 h1.52
  text "ARRAY/PANEL:" at 287.87,74.602 h1.52
  text "CUT AND TRIM PER M1 BOARD OUTLINE" at 314.819,74.393 h1.52
  text "N.C. ROUTE" at 314.819,70.94 h1.52
  text "X" at 332.295,70.94 h1.52
  text "V. SCORE" at 336.816,70.94 h1.52
  text "CERTIFICATION:" at 287.87,67.66 h1.52
  text "MATERIALS AND WORKMANSHIP FOR ALL PCBS" at 306.285,67.66 h1.52
  text "TO MEET OR EXCEED THE REQUIREMENTS OF:" at 306.285,65.271 h1.52
  text "X" at 297.078,62.003 h1.52
  text "ANSI IPC-A-600F CLASS ->" at 300.329,62.003 h1.52
  text "X" at 342.188,62.003 h1.52
  text "2" at 344.982,62.003 h1.52
  text "1" at 336.981,61.965 h1.52
  text "3" at 353.973,61.965 h1.52
  text "X" at 317.702,58.252 h1.52
  text "RoHS" at 320.953,58.252 h1.52
  text "OTHER" at 337.321,58.252 h1.52
  text "PER ORDER" at 347.407,58.252 h1.52
  text "ALL BOARDS MUST MEET OR EXCEED UL94-V0 REQUIREMENTS." at 288.569,54.345 h1.52
  text "PCB MUST BEAR THE UL94V-0 UL REGISTERED MATERIAL ID NUMBER" at 288.569,51.397 h1.52
  text "ADDITIONAL REQUIREMENTS:" at 287.87,47.094 h1.52
  text "MICROSECTION:" at 289.769,44.373 h1.52
  text "YES" at 312.775,44.373 h1.52
  text "REQUIRED" at 334.657,40.707 h1.52
  text "BARE BOARD ELEC. TEST:" at 289.769,40.634 h1.52
  text "NONE" at 322.935,40.634 h1.52
  text "X" at 331.66,40.634 h1.52
  text "PER ORDER" at 349.693,40.634 h1.52
  text "XX MIL VIAS REQUIRE NON-CONDUCTIVE FILL AND PLANARIZE" at 294.04,35.428 h1.5
  text "XX MIL VIAS REQUIRE CONDUCTIVE FILL AND PLANARIZE" at 294.243,32.787 h1.52
  text "OUTER XX MIL TRACES REQUIRE 50 OHM SINGLE-ENDED IMPEDANCE" at 294.218,28.637 h1.47
  text "LAYER 2 & 3 (INNER LAYERS) XX MIL WIDE, XX MIL SPACE / TRACES REQUIRE 100 OHM DIFFERENTIAL IMPEDANCE" at 294.015,22.65 h1.52
  text ".Layer_Name" at 14.656,-21.806 h1.52
M11 Gerber Information:
  lines w0.254: -7.417,-23.626 160.223,-23.626 ; -7.417,-18.462 160.274,-18.462 ; -7.417,-13.297 -7.417,-28.791 94.31,-28.791 160.274,-28.791 160.274,-13.297 -7.404,-13.297 -7.404,-28.791 32.614,-28.791 ; 55.194,-28.791 55.194,-13.297 ; 87.376,-18.462 87.376,-13.297 ; 108.712,-18.462 108.712,-13.297 ; 124.511,-28.956 124.511,-23.804
  text "ALL ARTWORK VIEWED FROM TOP SIDE" at -5.804,-16.654 h1.52
  text "BOARD #:" at 57.099,-16.654 h1.52
  text ".PRJ_Number" at 70.955,-16.654 h1.52
  text "REV:" at 92.405,-16.654 h1.52
  text ".PCB_Rev" at 99.809,-16.654 h1.52
  text "SVN REV:" at 113.69,-16.654 h1.52
  text ".VersionControl_RevNumber" at 126.543,-16.654 h1.52
  text "LAYER NAME =" at -5.804,-21.806 h1.52
  text "TID #:" at 57.099,-21.819 h1.52
  text ".TID" at 70.955,-21.819 h1.52
  text "PLOT NAME =" at -5.804,-27.034 h1.52
  text ".plot_File_Name" at 14.656,-27.034 h1.52
  text "GENERATED    :" at 57.15,-27.034 h1.52
  text ".Print_Date" at 79.235,-27.034 h1.52
  text ".Print_Time" at 97.752,-27.034 h1.52
  text "TEXAS INSTRUMENTS" at 129.87,-27.034 h1.52
M12 Stackup:
  drawing of 399 lines, arcs and shapes, not listed
  text "Layer" at 249.469,200.023 h1.52
  text "Name" at 259.88,200.023 h1.52
  text "Material" at 293.653,200.023 h1.52
  text "Thickness" at 308.889,200.023 h1.52
  text "Constant" at 325.395,200.023 h1.52
  text "Board Layer Stack" at 339.869,200.023 h1.52
  text "Top Overlay" at 259.88,196.975 h1.52
  text "Top Solder" at 259.88,193.927 h1.52
  text "SM-001" at 293.653,193.927 h1.52
  text "1.00mil" at 308.889,193.927 h1.52
  text "4" at 325.395,193.927 h1.52
  text "Top Surface Finish" at 259.88,190.879 h1.52
  text "PbSn" at 293.653,190.879 h1.52
  text "0.79mil" at 308.889,190.879 h1.52
  text "1" at 249.469,187.831 h1.52
  text "Top Layer" at 259.88,187.831 h1.52
  text "CF-004" at 293.653,187.831 h1.52
  text "1.38mil" at 308.889,187.831 h1.52
  text "Dielectric 1" at 259.88,184.783 h1.52
  text "PP-017" at 293.653,184.783 h1.52
  text "5.10mil" at 308.889,184.783 h1.52
  text "4.3" at 325.395,184.783 h1.52
  text "Dielectric 2" at 259.88,181.735 h1.52
  text "PP-017" at 293.653,181.735 h1.52
  text "5.10mil" at 308.889,181.735 h1.52
  text "4.3" at 325.395,181.735 h1.52
  text "2" at 249.469,178.687 h1.52
  text "Int1 (GND)" at 259.88,178.687 h1.52
  text "CF-004" at 293.653,178.687 h1.52
  text "1.38mil" at 308.889,178.687 h1.52
  text "Dielectric 3" at 259.88,175.639 h1.52
  text "Core-028" at 293.653,175.639 h1.52
  text "10.00mil" at 308.889,175.639 h1.52
  text "4.3" at 325.395,175.639 h1.52
  text "3" at 249.469,172.591 h1.52
  text "Int2 (PWR)" at 259.88,172.591 h1.52
  text "CF-004" at 293.653,172.591 h1.52
  text "1.38mil" at 308.889,172.591 h1.52
  text "Dielectric 4" at 259.88,169.543 h1.52
  text "PP-017" at 293.653,169.543 h1.52
  text "5.10mil" at 308.889,169.543 h1.52
  text "4.3" at 325.395,169.543 h1.52
  text "Dielectric 5" at 259.88,166.495 h1.52
  text "PP-017" at 293.653,166.495 h1.52
  text "5.10mil" at 308.889,166.495 h1.52
  text "4.3" at 325.395,166.495 h1.52
  text "4" at 249.469,163.447 h1.52
  text "Bottom Layer" at 259.88,163.447 h1.52
  text "CF-004" at 293.653,163.447 h1.52
  text "1.38mil" at 308.889,163.447 h1.52
  text "Bottom Surface Finish" at 259.88,160.399 h1.52
  text "PbSn" at 293.653,160.399 h1.52
  text "0.79mil" at 308.889,160.399 h1.52
  text "Bottom Solder" at 259.88,157.351 h1.52
  text "SM-001" at 293.653,157.351 h1.52
  text "1.00mil" at 308.889,157.351 h1.52
  text "4" at 325.395,157.351 h1.52
  text "Bottom Overlay" at 259.88,154.303 h1.52
  text ".Layer_Name" at 14.656,-21.806 h1.52
M13 Component Bodies Top:
  text ".Layer_Name" at 14.656,-21.806 h1.52
M14 Component Bodies Bottom:
  text ".Layer_Name" at 14.656,-21.806 h1.52
M15 Courtyards Top:
  text ".Layer_Name" at 14.656,-21.806 h1.52
M16 Courtyards Bottom:
  text ".Layer_Name" at 14.656,-21.806 h1.52
Drill Drawing:
  circle w0.254: c136.238,80.415 r0.702
  lines w0.254: 135.537,67.434 135.888,67.434 136.238,67.083 136.589,67.434 136.94,67.434 136.589,67.785 136.94,68.135 136.589,68.135 136.238,68.486 135.888,68.135 135.537,68.135 135.888,67.785 135.537,67.434 ; 135.537,71.644 136.94,71.644 136.238,70.241 135.537,71.644 ; 135.537,73.398 136.238,73.749 136.94,73.398 136.589,74.1 136.94,74.802 136.238,74.451 135.537,74.802 135.888,74.1 135.537,73.398 ; 135.537,76.907 135.888,76.907 135.888,76.556 136.589,76.556 136.589,76.907 136.94,76.907 136.94,77.609 136.589,77.609 136.589,77.959 135.888,77.959 135.888,77.609 135.537,77.609 135.537,76.907 ; 135.537,82.871 136.94,82.871 136.94,84.275 135.537,84.275 135.537,82.871
  lines w0.305: 134.264,66.136 216.344,66.136 ; 134.264,85.082 216.344,85.082 ; 142.846,62.978 142.846,88.24 ; 151.279,62.978 151.279,88.24 ; 167.448,62.978 167.448,88.24 ; 174.03,62.978 174.03,88.24 ; 183.559,62.978 183.559,88.24 ; 201.957,62.978 201.957,88.24 ; 134.264,62.978 216.344,62.978 216.344,88.24 134.264,88.24 134.264,62.978
  text "Symbol" at 136.159,86.029 h1.83
  text "Quantity" at 143.793,86.029 h1.83
  text "Finished Hole Size" at 152.226,86.029 h1.83
  text "Plated" at 168.395,86.029 h1.83
  text "Hole Type" at 174.977,86.029 h1.83
  text "Drill Layer Pair" at 184.506,86.029 h1.83
  text "Hole Tolerance" at 202.904,86.029 h1.83
  text "24" at 143.793,82.871 h1.52
  text "7.87mil (0.200mm)" at 152.226,82.871 h1.52
  text "PTH" at 168.395,82.871 h1.52
  text "Round" at 174.977,82.871 h1.52
  text "Top Layer - Bottom Layer" at 184.506,82.871 h1.52
  text "50" at 143.793,79.714 h1.52
  text "12.60mil (0.320mm)" at 152.226,79.714 h1.52
  text "PTH" at 168.395,79.714 h1.52
  text "Round" at 174.977,79.714 h1.52
  text "Top Layer - Bottom Layer" at 184.506,79.714 h1.52
  text "8" at 143.793,76.556 h1.52
  text "23.62mil (0.600mm)" at 152.226,76.556 h1.52
  text "PTH" at 168.395,76.556 h1.52
  text "Round" at 174.977,76.556 h1.52
  text "Top Layer - Bottom Layer" at 184.506,76.556 h1.52
  text "8" at 143.793,73.398 h1.52
  text "27.56mil (0.700mm)" at 152.226,73.398 h1.52
  text "PTH" at 168.395,73.398 h1.52
  text "Round" at 174.977,73.398 h1.52
  text "Top Layer - Bottom Layer" at 184.506,73.398 h1.52
  text "+/-1.97mil" at 202.904,73.398 h1.52
  text "16" at 143.793,70.241 h1.52
  text "27.56mil (0.700mm)" at 152.226,70.241 h1.52
  text "PTH" at 168.395,70.241 h1.52
  text "Round" at 174.977,70.241 h1.52
  text "Top Layer - Bottom Layer" at 184.506,70.241 h1.52
  text "2" at 143.793,67.083 h1.52
  text "29.53mil (0.750mm)" at 152.226,67.083 h1.52
  text "PTH" at 168.395,67.083 h1.52
  text "Round" at 174.977,67.083 h1.52
  text "Top Layer - Bottom Layer" at 184.506,67.083 h1.52
  text "108 Total" at 143.793,63.925 h1.52
  text ".Layer_Name" at 14.656,-21.806 h1.52
M17 Embedded Cavity:
  text ".Layer_Name" at 14.656,-21.806 h1.52
M18 Embedded Assembly:
  text ".Layer_Name" at 14.656,-21.806 h1.52
M19 Embedded Keepout:
  text ".Layer_Name" at 14.656,-21.806 h1.52

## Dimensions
0,-10.16 to 25.4,-10.16 on M2 Board Dimensions
0,0 to 0,30 on M2 Board Dimensions
0,0 to 35,0 on M2 Board Dimensions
